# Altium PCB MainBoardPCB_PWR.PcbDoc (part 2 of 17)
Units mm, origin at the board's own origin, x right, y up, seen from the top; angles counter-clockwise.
Board outline 333.63 x 349.38 mm, 16 copper layers (L1, L2 (GND), L3 (Sign), L4 (GND), L5 (Sign), L6 (PWR/GND), L7(PWR/GND), L8 (PWR/GND), L9 (PWR/GND), L10 (PWR/GND), L11 (PWR/GND), L12 (Sign), L13 (GND), L14 (Sign), L15 (GND), L16), stack 2.503 mm thick; 2187 components, 1615 nets, 7987 pads, 1695 vias.
Unrouted connection lines stored in the file: 4757.
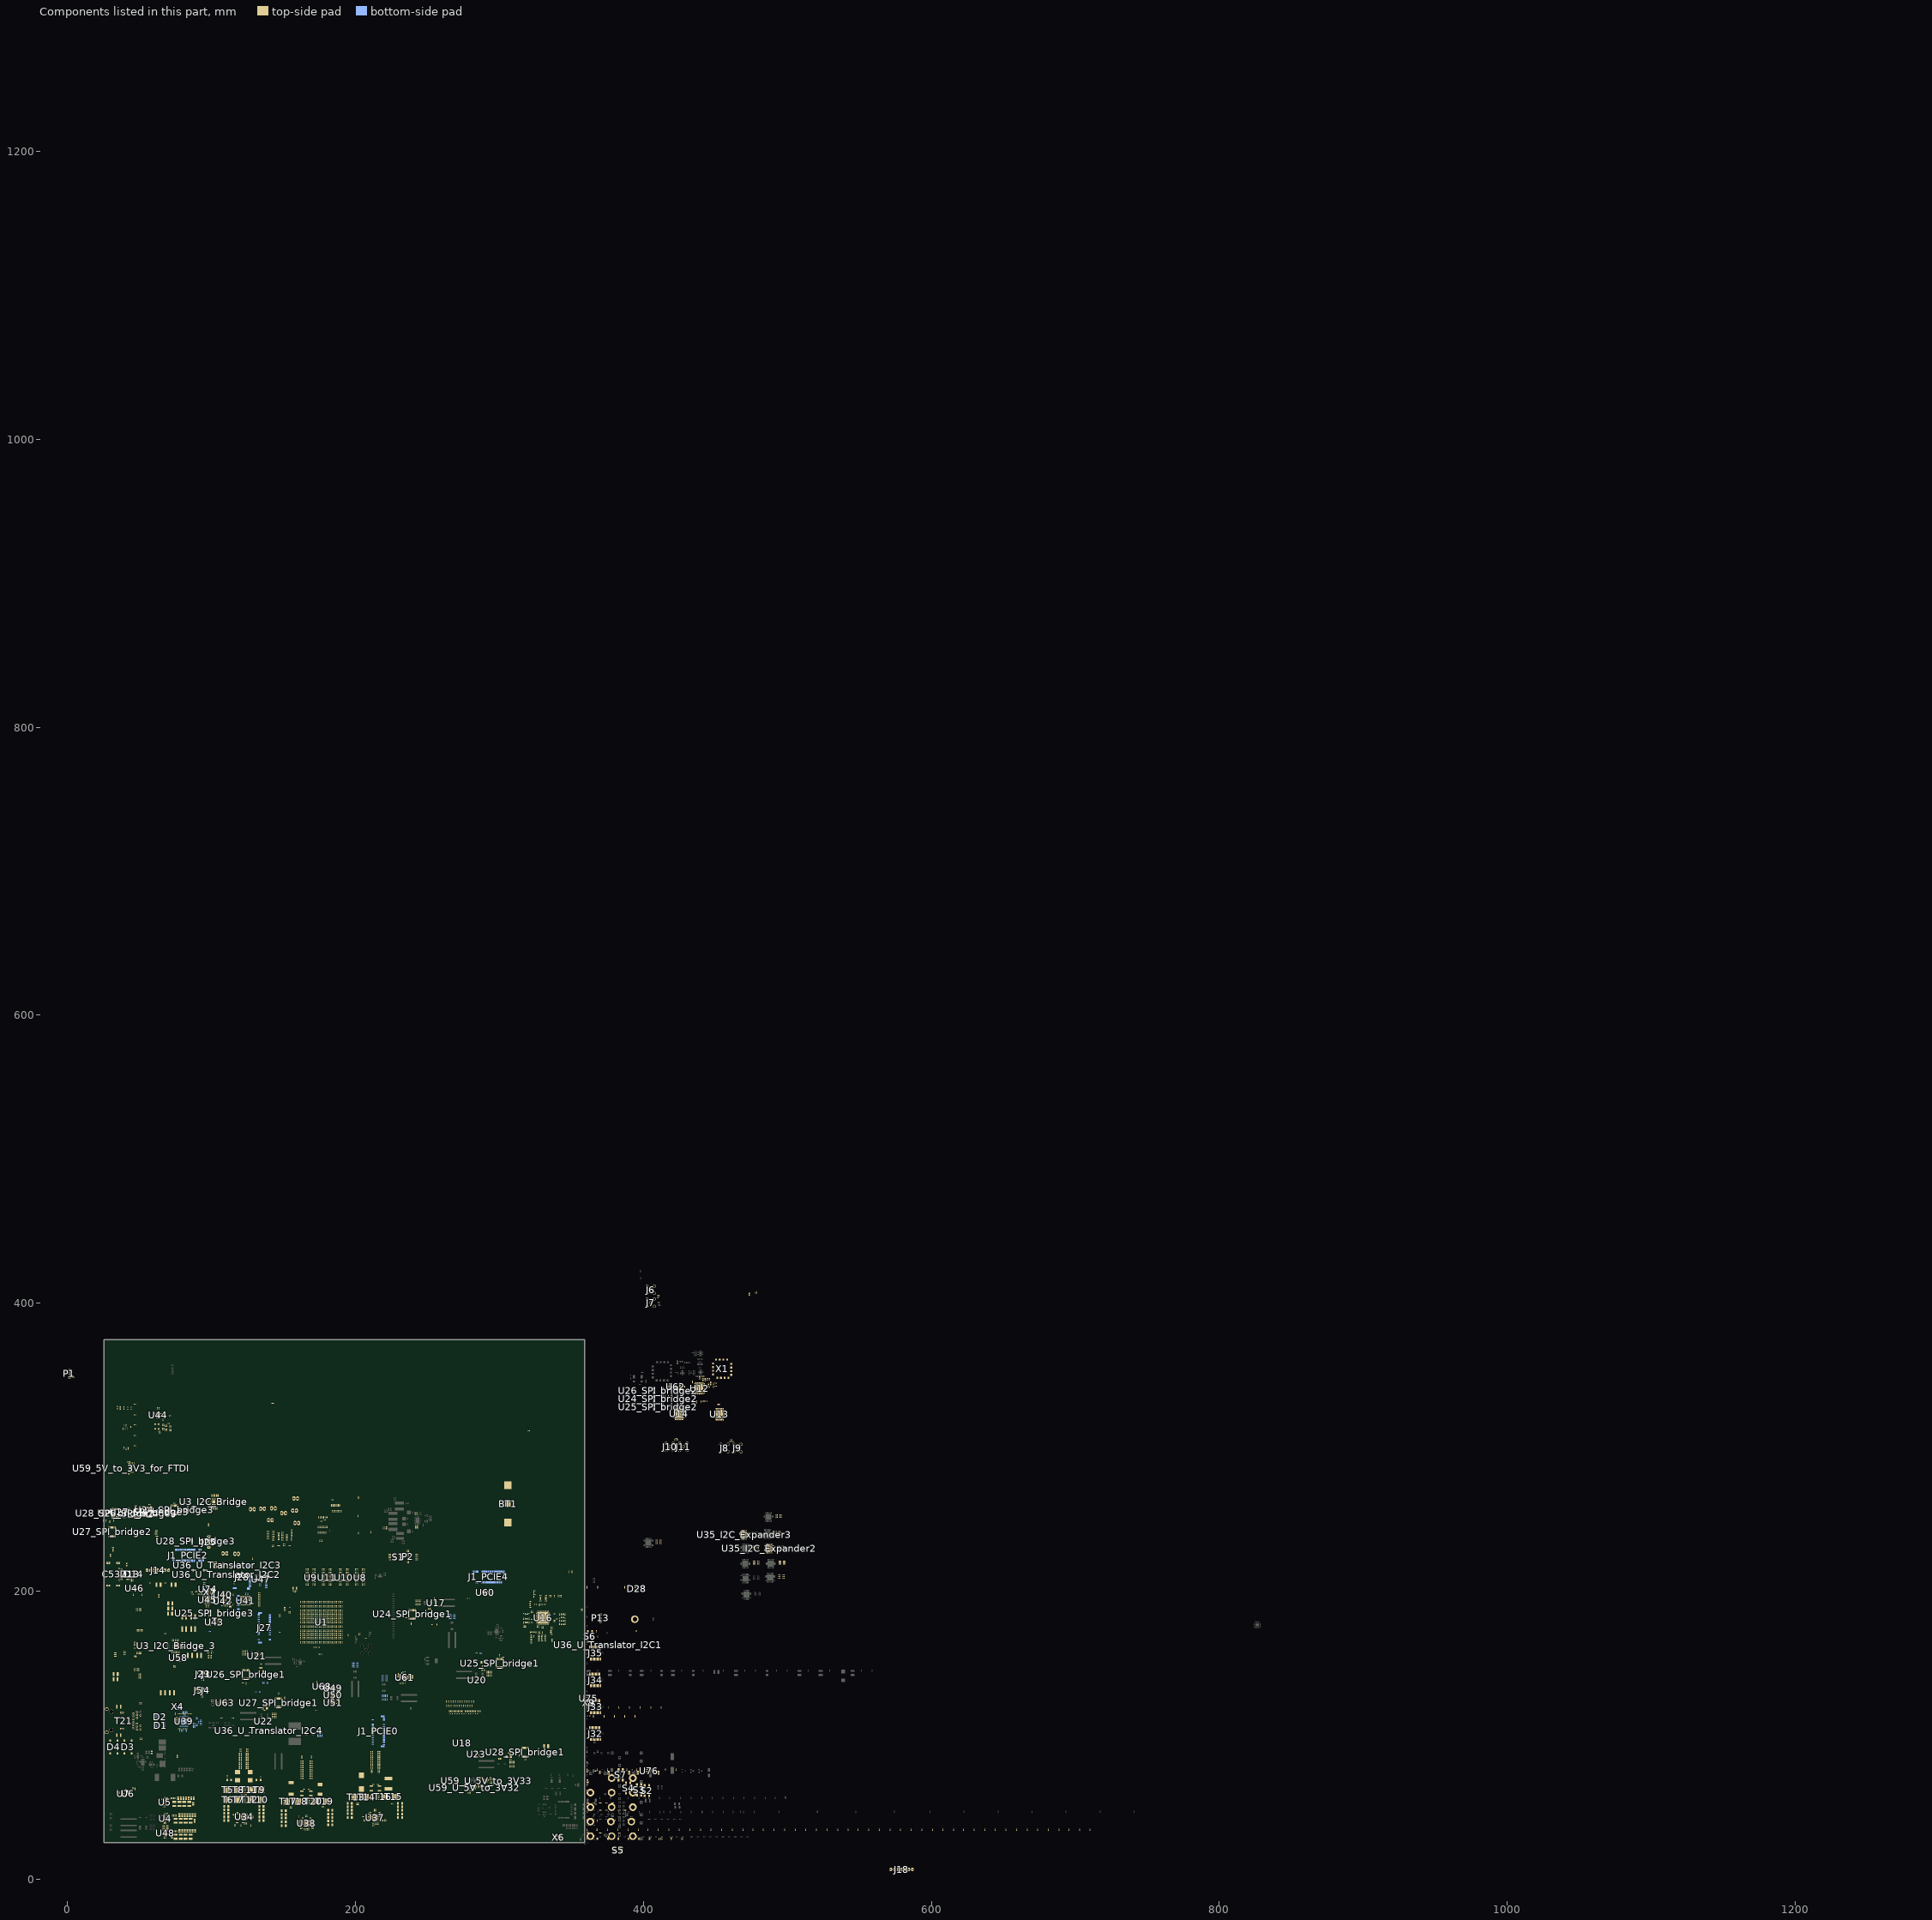
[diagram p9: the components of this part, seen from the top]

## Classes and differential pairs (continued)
net class Bank225_MGTREFx_to_C: CLK_Q225_T1_N CLK_Q225_T1_P
net class Bank225_MGTREFx_C: Bank225_MGTREF0_C_N Bank225_MGTREF0_C_P Bank225_MGTREF1_C_N Bank225_MGTREF1_C_P
net class Bank224_MGTREFx_to_C: CLK_Q224_T1_N CLK_Q224_T1_P
net class Bank224_MGTREFx_C: Bank224_MGTREF0_C_N Bank224_MGTREF0_C_P Bank224_MGTREF1_C_N Bank224_MGTREF1_C_P
net class Bank223_MGTREFx_to_C: CLK_Q223_T1_N CLK_Q223_T1_P
net class Bank223_MGTREFx_C: Bank223_MGTREF0_C_N Bank223_MGTREF0_C_P Bank223_MGTREF1_C_N Bank223_MGTREF1_C_P
component class U_Translator_I2C4: TP60_U_Translator_I2C4 TP61_U_Translator_I2C4 U36_U_Translator_I2C4
differential pair class Diff_90: USB_D USB_RX USB_RX_C USB_TX USB_TX_C
net class USB_2.0: USB_D_N USB_D_P
net class SYNC: SYNC_PCIE0_N SYNC_PCIE0_P SYNC_PCIE1_N SYNC_PCIE1_P SYNC_PCIE2_N SYNC_PCIE2_P SYNC_PCIE3_N SYNC_PCIE3_P SYNC_PCIE4_N SYNC_PCIE4_P
net class Single_45: USB_D_N USB_D_P USB_RX_C_N USB_RX_C_P USB_RX_N USB_RX_P USB_TX_C_N USB_TX_C_P USB_TX_N USB_TX_P
component class U_CAN: C585 P6 R446 R447 U63 U75
differential pair class Diff_100: B223_Rx0 B223_Rx1 B223_Rx2 B223_Rx3 B223_Tx0_to_C B223_Tx0C_to_B B223_Tx1_to_C B223_Tx1C_to_B B223_Tx2_to_C B223_Tx2C_to_B B223_Tx3_to_C B223_Tx3C_to_B B224_Rx0 B224_Rx1 B224_Rx2 B224_Rx3 B224_Tx0_to_C B224_Tx0C_to_B B224_Tx1_to_C B224_Tx1C_to_B B224_Tx2_to_C B224_Tx2C_to_B B224_Tx3_to_C B224_Tx3C_to_B B225_Rx0 B225_Rx1 B225_Rx2 B225_Rx3 B225_Tx0_to_C B225_Tx0C_to_B B225_Tx1_to_C B225_Tx1C_to_B B225_Tx2_to_C B225_Tx2C_to_B B225_Tx3_to_C B225_Tx3C_to_B Bank223_MGTREF0_C Bank223_MGTREF1_C Bank224_MGTREF0_C Bank224_MGTREF1_C Bank225_MGTREF0_C Bank225_MGTREF1_C Bank505_MGTRREF0_C Bank505_MGTRREF2_C Bank505_MGTRREF3_C CLK_100 CLK_Fanout_In CLK_GTR_T1 CLK_GTR_T2 CLK_GTR_T3 CLK_Hi_Rail1 CLK_Hi_Rail1_SysRef CLK_Hi_Rail2 CLK_Hi_Rail2_SysRef CLK_M_OSC_In CLK_NVME_Conn CLK_Q223_T1 CLK_Q224_T1 CLK_Q225_T1 CLK_Q226_T1 CLK_SMA0 CLK_SMA0_C CLK_SMA1 CLK_SMA1_C CLK_SMA2 CLK_SMA2_C Data_2_RX_PCIE0 Data_2_RX_PCIE1 Data_2_RX_PCIE2 Data_2_RX_PCIE3 Data_2_TX_PCIE0 Data_2_TX_PCIE1 Data_2_TX_PCIE2 Data_2_TX_PCIE3 Data_3_RX_PCIE0 Data_3_RX_PCIE1 Data_3_RX_PCIE2 Data_3_RX_PCIE3 Data_3_TX_PCIE0 Data_3_TX_PCIE1 Data_3_TX_PCIE2 Data_3_TX_PCIE3 LTC6952_1_REF LTC6952_2_REF LTC6952_2_REF_SMA LTC6952_3_REF LTC6952_3_REF_SMA NVME_C_RX_1 NVME_C_RX_O NVME_C_TX_1 NVME_C_TX_O NVMe_CLK NVMe_Rx_0 NVMe_Rx_1 NVMe_Tx_0 NVMe_Tx_1 Osc_in_Si53323_2 OSC_Out_DIV PCIE0_CLK PCIE0_Sync PCIE0_SysRef PCIE0_SysRef_FPGA PCIE1_CLK PCIE1_Sync PCIE1_SysRef PCIE1_SysRef_FPGA PCIE2_CLK PCIE2_Sync PCIE2_SysRef PCIE2_SysRef_FPGA PCIE3_CLK PCIE3_Sync PCIE3_SysRef PCIE3_SysRef_FPGA PCIE4_CLK PCIE4_Sync PCIE4_SysRef PCIE4_SysRef_FPGA RefClk_Si53323 SFP0_Rx SFP0_Tx SFP1_Rx SFP1_Tx SFP2_Rx SFP2_Tx SFP3_Rx SFP3_Tx SGMI_C_Rx SGMI_C_Tx SGMI_CLK_C_Out SGMI_CLK_Out SGMI_Rx SGMI_Tx Si53323_1_Q1 Si53323_1_Q2 Si53323_1_Q2_LVDS Si53323_2_CLK1 Si53323_2_Q1 Si53323_2_Q2 Si53323_2_Q2_LVDS SYNC_PCIE0 SYNC_PCIE1 SYNC_PCIE2 SYNC_PCIE3 SYNC_PCIE4 SYSREF_PCIE0 SYSREF_PCIE1 SYSREF_PCIE2 SYSREF_PCIE3 SYSREF_PCIE4 TD_A TD_B TD_C TD_D WR_LMK_CLK_HF1 WR_LMK_CLK_HF2 WR_LMK_CLK_IN WR_Source_CLK
channel class Translator_I2C: U_Translator_I2C1 U_Translator_I2C2 U_Translator_I2C3
channel class 5V_to_3V3: 5V_to_3V3_for_FTDI U_5V_to_3V32 U_5V_to_3V33
net class SYSREF: PCIE0_SysRef_N PCIE0_SysRef_P PCIE1_SysRef_N PCIE1_SysRef_P PCIE2_SysRef_N PCIE2_SysRef_P PCIE3_SysRef_N PCIE3_SysRef_P PCIE4_SysRef_N PCIE4_SysRef_P
net class SGMII_DATA_TO_C: SGMI_Rx_N SGMI_Rx_P SGMI_Tx_N SGMI_Tx_P
net class SGMII_DATA_C_FPGA: SGMI_C_Rx_N SGMI_C_Rx_P SGMI_C_Tx_N SGMI_C_Tx_P
net class Distr_to_Conn: PCIE0_CLK_N PCIE0_CLK_P PCIE1_CLK_N PCIE1_CLK_P PCIE2_CLK_N PCIE2_CLK_P PCIE3_CLK_N PCIE3_CLK_P PCIE4_CLK_N PCIE4_CLK_P
net class SFP_diff: SFP0_Rx_N SFP0_Rx_P SFP0_Tx_N SFP0_Tx_P SFP1_Rx_N SFP1_Rx_P SFP1_Tx_N SFP1_Tx_P SFP2_Rx_N SFP2_Rx_P SFP2_Tx_N SFP2_Tx_P SFP3_Rx_N SFP3_Rx_P SFP3_Tx_N SFP3_Tx_P
net class Conn_to_C: B223_Tx0_to_C_N B223_Tx0_to_C_P B223_Tx1_to_C_N B223_Tx1_to_C_P B223_Tx2_to_C_N B223_Tx2_to_C_P B223_Tx3_to_C_N B223_Tx3_to_C_P B224_Tx0_to_C_N B224_Tx0_to_C_P B224_Tx1_to_C_N B224_Tx1_to_C_P B224_Tx2_to_C_N B224_Tx2_to_C_P B224_Tx3_to_C_N B224_Tx3_to_C_P B225_Tx0_to_C_N B225_Tx0_to_C_P B225_Tx1_to_C_N B225_Tx1_to_C_P B225_Tx2_to_C_N B225_Tx2_to_C_P B225_Tx3_to_C_N B225_Tx3_to_C_P Data_2_TX_PCIE0_N Data_2_TX_PCIE0_P Data_2_TX_PCIE1_N Data_2_TX_PCIE1_P Data_2_TX_PCIE2_N Data_2_TX_PCIE2_P Data_2_TX_PCIE3_N Data_2_TX_PCIE3_P Data_3_TX_PCIE0_N Data_3_TX_PCIE0_P Data_3_TX_PCIE1_N Data_3_TX_PCIE1_P Data_3_TX_PCIE2_N Data_3_TX_PCIE2_P Data_3_TX_PCIE3_N Data_3_TX_PCIE3_P
net class C_to_Bank225: B225_Tx0C_to_B_N B225_Tx0C_to_B_P B225_Tx1C_to_B_N B225_Tx1C_to_B_P B225_Tx2C_to_B_N B225_Tx2C_to_B_P B225_Tx3C_to_B_N B225_Tx3C_to_B_P
net class C_to_Bank224: B224_Tx0C_to_B_N B224_Tx0C_to_B_P B224_Tx1C_to_B_N B224_Tx1C_to_B_P B224_Tx2C_to_B_N B224_Tx2C_to_B_P B224_Tx3C_to_B_N B224_Tx3C_to_B_P
net class C_to_Bank223: B223_Rx0_N B223_Rx0_P B223_Rx1_N B223_Rx1_P B223_Rx2_N B223_Rx2_P B223_Rx3_N B223_Rx3_P B223_Tx0C_to_B_N B223_Tx0C_to_B_P B223_Tx1C_to_B_N B223_Tx1C_to_B_P B223_Tx2C_to_B_N B223_Tx2C_to_B_P B223_Tx3C_to_B_N B223_Tx3C_to_B_P
net class Bank_to_Conn: B223_Rx0_N B223_Rx0_P B223_Rx1_N B223_Rx1_P B223_Rx2_N B223_Rx2_P B223_Rx3_N B223_Rx3_P B224_Rx0_N B224_Rx0_P B224_Rx1_N B224_Rx1_P B224_Rx2_N B224_Rx2_P B224_Rx3_N B224_Rx3_P B225_Rx0_N B225_Rx0_P B225_Rx1_N B225_Rx1_P B225_Rx2_N B225_Rx2_P B225_Rx3_N B225_Rx3_P Data_2_RX_PCIE0_N Data_2_RX_PCIE0_P Data_2_RX_PCIE1_N Data_2_RX_PCIE1_P Data_2_RX_PCIE2_N Data_2_RX_PCIE2_P Data_2_RX_PCIE3_N Data_2_RX_PCIE3_P Data_3_RX_PCIE0_N Data_3_RX_PCIE0_P Data_3_RX_PCIE1_N Data_3_RX_PCIE1_P Data_3_RX_PCIE2_N Data_3_RX_PCIE2_P Data_3_RX_PCIE3_N Data_3_RX_PCIE3_P PCIE0_Prsnt1 PCIE1_Prsnt1 PCIE2_Prsnt1 PCIE3_Prsnt1 PCIE4_Prsnt1
component class U_Translator_I2C3: TP60_U_Translator_I2C3 TP61_U_Translator_I2C3 U36_U_Translator_I2C3
component class U_Translator_I2C2: TP60_U_Translator_I2C2 TP61_U_Translator_I2C2 U36_U_Translator_I2C2
component class U_Translator_I2C1: TP60_U_Translator_I2C1 TP61_U_Translator_I2C1 U36_U_Translator_I2C1
component class U_TPS7A88_5V_Dual_3: C572 C573 C574 C575 C576 C577 C578 C579 R436 R437 R438 R439 R440 R441 U61
component class U_LT3042_12V_5V_LNLDO: C580 C581 C582 C583 C584 FB34 R442 R443 R444 R445 U62
component class U_ADP1741_3: C568 C569 C570 C571 FB33 R433 R434 U60
component class U_5V_to_3V33: C563_U_5V_to_3V33 C564_U_5V_to_3V33 C565_U_5V_to_3V33 C566_U_5V_to_3V33 C567_U_5V_to_3V33 R430_U_5V_to_3V33 R431_U_5V_to_3V33 R432_U_5V_to_3V33 U59_U_5V_to_3V33
component class U_5V_to_3V32: C563_U_5V_to_3V32 C564_U_5V_to_3V32 C565_U_5V_to_3V32 C566_U_5V_to_3V32 C567_U_5V_to_3V32 R430_U_5V_to_3V32 R431_U_5V_to_3V32 R432_U_5V_to_3V32 U59_U_5V_to_3V32
component class SPI_bridge3: R231_SPI_bridge3 R232_SPI_bridge3 R233_SPI_bridge3 R234_SPI_bridge3 R235_SPI_bridge3 R236_SPI_bridge3 R237_SPI_bridge3 R238_SPI_bridge3 R239_SPI_bridge3 R240_SPI_bridge3 TP50_SPI_bridge3 TP51_SPI_bridge3 TP52_SPI_bridge3 TP53_SPI_bridge3 TP54_SPI_bridge3 TP55_SPI_bridge3 TP56_SPI_bridge3 TP57_SPI_bridge3 TP58_SPI_bridge3 TP59_SPI_bridge3 U24_SPI_bridge3 U25_SPI_bridge3 U26_SPI_bridge3 U27_SPI_bridge3 U28_SPI_bridge3
component class Ram_Power: C219 C220 C221 C222 C223 C224 C225 C226 C227 C228 C229 C230 C231 C232 C233 C234 C235 C236 C237 C238 C239 C240 C241 C242 C243 C244 C245 C246 C247 C248 C249 C250 C251 C252 C253 C254 C255 C256 C257 C258 C259 C260 C261 C262 C263 C264 C265 C266 C782 C783 C784 C785 C786 C787 C788 C789 R165 R166 R167 R168 R169 R170 R171 R172
component class PS_Config: C531 C532 C533 C534 C535 C536 D5 D6 D7 D8 D9 D10 D11 D12 P2 P3 P4 P5 R346 R347 R348 R349 R350 R351 R352 R353 R354 R355 R356 R357 R358 R359 R360 R361 R367 R368 R369 R370 R371 R372 R373 R374 R375 R716 R717 R718 R719 R720 S1 S2 S3 S4 U43 U44 X5 X6
component class IMU: C561 C562 R425 R426 R429 R600 R601 U58
component class GTR: C525 C526 C527 C528 C529 C530 C649 C651 C653 C677 C715 C716 C717 C718 R69 R70 R126
component class "Bank 225": C291 C292 C293 C294 C295 C296 C297 C298 C299 C300 C301 C302
component class "Bank 224": C279 C280 C281 C282 C283 C284 C285 C286 C287 C288 C289 C290
component class "Bank 223": C267 C268 C269 C270 C271 C272 C273 C274 C275 C276 C277 C278
component class 5V_to_3V3_for_FTDI: C563_5V_to_3V3_for_FTDI C564_5V_to_3V3_for_FTDI C565_5V_to_3V3_for_FTDI C566_5V_to_3V3_for_FTDI C567_5V_to_3V3_for_FTDI R430_5V_to_3V3_for_FTDI R431_5V_to_3V3_for_FTDI R432_5V_to_3V3_for_FTDI U59_5V_to_3V3_for_FTDI
component class µSD: C544 C545 C546 C547 FB29 J28 R381 R382 R383 U47
component class U_Power_Ethernet: C550 C551 C552 C553 C554 C555 C654 C655 C656 C657 R391 R392 R393 R394 R396 R397 R399 R632 R633 R634 U49 U50 U51 U68
component class U_Power_ADP1850_Dual_2: C430 C431 C432 C433 C434 C435 C436 C437 C438 C439 C440 C441 C442 C443 C444 C445 C446 C447 C448 C449 C450 C451 C452 C453 C454 C455 C456 C457 C458 C459 C460 C461 C462 C463 C464 C465 C466 C467 C468 C469 C470 C548 C549 C645 C646 C647 C648 C650 C652 L19 L20 R302 R303 R306 R307 R310 R312 R313 R314 R315 R316 R317 R318 R625 R626 R627 R628 R629 R631 R686 R687 T17 T18 T19 T20 U38
component class U_HI_Curr_ADP1850_3: C389 C390 C391 C392 C393 C394 C395 C396 C397 C398 C399 C400 C401 C402 C403 C404 C405 C406 C407 C408 C409 C410 C411 C412 C413 C414 C415 C416 C417 C418 C419 C420 C421 C422 C423 C424 C425 C426 C427 C428 C429 C637 C638 C639 C640 C641 C642 C643 C644 L11 L12 R285 R287 R288 R289 R290 R292 R293 R294 R295 R296 R297 R298 R299 R300 R619 R620 R621 R622 R623 R624 T13 T14 T15 T16 U37
component class NVMe: J27 R541 R542
component class "Zasilanie CLK": C55 C56 C57 C58 C59 C60 C61 C62 C63 C64 C65 C66 C67 C68 C69 C70 C71 C72 C73 C74 C75 C76 C77 C78 C79 C80 C81 C82 C83 C84 C85 C86 C87 C88 C89 C90 C91 C92 C93 C94 C95 C96 C97 C98 C99 C100 C101 C102 C103 C104 C105 C106 C107 C108 C109 C110 C111 C112 C113 C114 C115 C116 C117 C118 C119 C120 C121 C122 C123 C124 C125 C126 C127 C128 C129 C130 C131 C132 C133 C134 C135 C136 C137 C138 C139 C140 C141 C142 C143 C144 C145 C146 C147 C148 C149 C150 C151 C152 C153 C154 C155 C156 C157 C158 C159 C160 C161 C162 C163 C164 C165 C166 C167 C168 C169 C170 C171 C172 C173 C174 C175 C176 C177 C178 C179 C180 C181 C182 C183 C184 C185 C186 C187 C188 C189 C190 C191 C192 C193 C194 C195 C196 C197 C198 C199 C200 C201 C202 C203 C204 C205 C206 FB2 FB3 FB4 FB5 FB6 FB7 FB8 FB9 FB10 FB11 FB12 FB13 FB14 FB15 FB16 FB17 FB18 FB19 FB20 FB21 FB22 FB35 FB36 R738 R739 R740 R741 R742 R743 U16
component class "Gigabit Eth": C471 C472 C473 C474 C475 C476 C479 C480 C481 C482 C483 C484 C485 C486 C487 C488 C489 C490 C491 C492 C493 C494 C495 C496 C497 C498 C499 C500 C501 C502 C503 C504 C505 C506 C507 C508 C509 C510 C511 C512 C513 C514 C790 D1 D2 D3 D4 R319 R320 R321 R322 R323 R324 R325 R326 R327 R328 R329 R330 R331 R332 R333 R334 R335 R336 R337 R338 R709 R710 R711 R712 R713 R714 R715 S7 T21 U39 U76 X4
component class Flash_Memory: C515 C516 C517 C518 C519 C520 C521 C522 C523 C524 C586 C587 FB25 R339 R340 R341 R342 R343 R344 R345 U40 U41 U42
component class PowerSelector: C4 C5 C6 C7 C8 C9 C10 C11 C12 C13 C14 C15 C16 C17 C18 C19 C20 C21 C22 C23 C24 C25 C26 C27 C28 C29 C30 C31 C32 C33 C34 C35 C766 C767 C768 C769 C770 C771 C772 C773 C774 C775 C776 C777 C778 C779 C780 C781 R11 R12 R13 R15 R17 R18 R19 R20 R21 R23 R25 R26 R27 R28 R29 R30 R630 R677 R678 R679 R680 R681 R682 R683 R684 R685 U4 U5 U6 U7 U48
component class USB3.0: C537 C538 C539 C540 C541 C542 C543 C728 C729 C730 C731 C732 C733 C734 C735 C736 C737 D13 D14 FB26 FB27 FB28 R376 R377 R378 R379 R380 R490 R491 U45 U46 U74 X7
channel class SPI_Muxes: SPI_bridge1 SPI_bridge2
channel class I2C_Expander: I2C_Expander2 I2C_Expander3 I2C_Expander4 I2C_Expander5
component class XilinxPower: B1 C627 C628 C629 C630 C631 C632 D28 FB38 FB39 FB40 FB41 FB42 R173 R276 R279 R282 R283 R286 R693 R694 R695 R696
component class "Xilinx Linux": J12 J13 J14 J15 J16 J17 J18 J19 J20 J21 J22 J23 J24 J25 P1 P13 R83 R84 R85 R86 R87 R88 R89 R90 R91 R92 R93 R94 R95 R96 R97 R98 R99 R100 R101 R102 R103 R104 R105 R106 R107 R108 R109 R110 R111 R112 R115 R116 R117 R118 R119 R120 R121 R122 R123 R362 R675 R737 R768 R769 R770 R771 R772 R773 R774 R775 R776 R777 R778 R779 R780 R781 R782 R783 R784 R785 R786 R787 R788 R789 R790 R791 R792 R793 R794 R795 R796 R797 R798 R799 R800 R801 R802 R803 R804 R805 R806 R807 R808 R809 R810 R811 R812 R813 R814 R815 R816 TP21 TP22 TP23 TP24 TP25 TP26 TP27 TP28 TP29 TP30 TP31 TP32 TP33 TP34 TP35 TP36 TP37 TP38 TP39 TP40 TP41 TP42
component class "WR CLK": C588 C589 C590 C591 C592 FB37 R1 R2 R125 R127 R128 R129 R130 R131 R132 R133 R134 R139 R311 R366 R498 R499 R540 R543 R544 R545 R692 S6 X9
component class U_HI_Curr_ADP1850_1: C345 C346 C347 C348 C349 C350 C351 C352 C353 C356 C357 C358 C359 C360 C361 C362 C363 C364 C365 C366 C367 C368 C369 C370 C371 C372 C373 C374 C375 C376 C377 C378 C379 C380 C381 C382 C383 C384 C385 C386 C387 C388 C633 C634 C635 C636 L9 L10 R268 R271 R272 R273 R275 R277 R278 R280 R610 R611 R612 R613 R614 R615 R616 T5 T6 T7 T8 T9 T10 T11 T12 U34
component class SPI_bridge2: R231_SPI_bridge2 R232_SPI_bridge2 R233_SPI_bridge2 R234_SPI_bridge2 R235_SPI_bridge2 R236_SPI_bridge2 R237_SPI_bridge2 R238_SPI_bridge2 R239_SPI_bridge2 R240_SPI_bridge2 TP50_SPI_bridge2 TP51_SPI_bridge2 TP52_SPI_bridge2 TP53_SPI_bridge2 TP54_SPI_bridge2 TP55_SPI_bridge2 TP56_SPI_bridge2 TP57_SPI_bridge2 TP58_SPI_bridge2 TP59_SPI_bridge2 U24_SPI_bridge2 U25_SPI_bridge2 U26_SPI_bridge2 U27_SPI_bridge2 U28_SPI_bridge2
component class SPI_bridge1: R231_SPI_bridge1 R232_SPI_bridge1 R233_SPI_bridge1 R234_SPI_bridge1 R235_SPI_bridge1 R236_SPI_bridge1 R237_SPI_bridge1 R238_SPI_bridge1 R239_SPI_bridge1 R240_SPI_bridge1 TP50_SPI_bridge1 TP51_SPI_bridge1 TP52_SPI_bridge1 TP53_SPI_bridge1 TP54_SPI_bridge1 TP55_SPI_bridge1 TP56_SPI_bridge1 TP57_SPI_bridge1 TP58_SPI_bridge1 TP59_SPI_bridge1 U24_SPI_bridge1 U25_SPI_bridge1 U26_SPI_bridge1 U27_SPI_bridge1 U28_SPI_bridge1
component class SFP3: C215 C216 C217 C218 J35 L7 L8 R155 R156 R157 R158 R161 R162 R163 R164
component class SFP2: C211 C212 C213 C214 J34 L5 L6 R145 R146 R147 R148 R151 R152 R153 R154
component class SFP1: C207 C208 C209 C210 J33 L3 L4 R135 R136 R137 R138 R141 R142 R143 R144
component class Ram: C36 R31 R32 R33 R34 R35 R36 R37 R38 R39 R40 R41 R42 R43 R44 R45 R46 R47 R48 R49 R50 R51 R52 R53 R54 R55 R56 R57 R58 R59 R60 R61 R62 R63 R64 U8 U9 U10 U11
component class Power4HighSpeed: R174 R175 R176 R177 R178 R179 R180 R181 R182 R183 R184 R185 R186 R187 R188 R189 R190 R191 R192 R193 R194 R195 R196 R197 R198 R199 R200 R201 R202 R203 R204 R205 R206 R207 R208 R209 R210 R211 R213 R215 R217 R219 R221 R222 R228 R602 R603 R604 R605 R606 U17 U20 U21 U22 U23
component class I2C_Expander2: C311_I2C_Expander2 U35_I2C_Expander2
component class I2C_Expander3: C311_I2C_Expander3 U35_I2C_Expander3
component class Ext_GPIO: R241 R242 R243 R244 R281 R400 R428 R492 R493 R494 R495 R496 R497 R500 R501 R502 R503 R504 R505 R508 R509 R510 R511 R512 R513 R516 R517 R518 R519 R520 R521 R524 R525 R526 R527 R528 R529 R599 R697 R698 R699 R700 R701 R702 R703 R704 R705 R706 R707 R708 R832 R833 R834 R835 R836 R837 R838 R839 R840 R841 TP62 TP63 TP64 TP65 TP66 TP67 TP68 TP69 TP70 TP71 TP72 TP73 TP74 TP75 TP76 TP77 TP78 TP79 TP80 TP81 TP82 TP83 TP84 TP85 TP86 TP87 TP88
component class HiCurrent: C331 C332 R14 R16 R22 R24 R266 R267 R269 R304 R388 R389 R390 R561 R562 R563 R564 R565 R566 R567 R568 R569 R570 R571 R572 R573 R574 R575 R576 R577 R578 R579 R580 R581 R582 R583 R584 R585 R586 R587 R588 R589 R590 R591 R592 S5 U18
component class PCIE4: C1_PCIE4 C2_PCIE4 C3_PCIE4 D1_PCIE4 FB1_PCIE4 J1_PCIE4 MP1_PCIE4 MP2_PCIE4 MP3_PCIE4
component class PCIE3: C1_PCIE3 C2_PCIE3 C3_PCIE3 D1_PCIE3 FB1_PCIE3 MP1_PCIE3 MP2_PCIE3 MP3_PCIE3
component class PCIE2: C1_PCIE2 C2_PCIE2 C3_PCIE2 D1_PCIE2 FB1_PCIE2 J1_PCIE2 MP1_PCIE2 MP2_PCIE2 MP3_PCIE2
component class PCIE1: C1_PCIE1 C2_PCIE1 C3_PCIE1 D1_PCIE1 FB1_PCIE1 MP1_PCIE1 MP2_PCIE1 MP3_PCIE1
component class PCIE0: C1_PCIE0 C2_PCIE0 C3_PCIE0 D1_PCIE0 FB1_PCIE0 J1_PCIE0 MP1_PCIE0 MP2_PCIE0 MP3_PCIE0
component class ClockDistrib: C41 C42 C43 C44 C45 C46 C47 C48 C49 C50 C51 C52 C53 C54 C334 C335 C593 C594 J2 J3 J4 J5 J6 J7 J8 J9 J10 J11 R75 R76 R77 R78 R79 R80 R81 R82 R270 R532 R533 R534 R535 R536 R537 R539 TP19 TP20 U12 U13 U14 X1
channel class PCIe: PCIE0 PCIE1 PCIE2 PCIE3 PCIE4
channel class I2C_Bridge: I2C_Bridge I2C_Bridge_3
component class "Bank 226": U1
component class SFP0: C37 C38 C39 C40 J32 L1 L2 R65 R66 R67 R68 R71 R72 R73 R74
component class I2C_Bridge_3: C303_I2C_Bridge_3 R3_I2C_Bridge_3 R4_I2C_Bridge_3 R5_I2C_Bridge_3 R6_I2C_Bridge_3 R7_I2C_Bridge_3 R8_I2C_Bridge_3 R9_I2C_Bridge_3 R10_I2C_Bridge_3 R223_I2C_Bridge_3 R224_I2C_Bridge_3 R225_I2C_Bridge_3 R226_I2C_Bridge_3 R227_I2C_Bridge_3 R558_I2C_Bridge_3 R559_I2C_Bridge_3 R560_I2C_Bridge_3 TP1_I2C_Bridge_3 TP2_I2C_Bridge_3 TP3_I2C_Bridge_3 TP4_I2C_Bridge_3 TP5_I2C_Bridge_3 TP6_I2C_Bridge_3 TP7_I2C_Bridge_3 TP8_I2C_Bridge_3 TP9_I2C_Bridge_3 TP10_I2C_Bridge_3 TP11_I2C_Bridge_3 TP12_I2C_Bridge_3 TP13_I2C_Bridge_3 TP14_I2C_Bridge_3 TP15_I2C_Bridge_3 TP16_I2C_Bridge_3 TP17_I2C_Bridge_3 TP18_I2C_Bridge_3 U3_I2C_Bridge_3
component class I2C_Bridge: C303_I2C_Bridge R3_I2C_Bridge R4_I2C_Bridge R5_I2C_Bridge R6_I2C_Bridge R7_I2C_Bridge R8_I2C_Bridge R9_I2C_Bridge R10_I2C_Bridge R223_I2C_Bridge R224_I2C_Bridge R225_I2C_Bridge R226_I2C_Bridge R227_I2C_Bridge R558_I2C_Bridge R559_I2C_Bridge R560_I2C_Bridge TP1_I2C_Bridge TP2_I2C_Bridge TP3_I2C_Bridge TP4_I2C_Bridge TP5_I2C_Bridge TP6_I2C_Bridge TP7_I2C_Bridge TP8_I2C_Bridge TP9_I2C_Bridge TP10_I2C_Bridge TP11_I2C_Bridge TP12_I2C_Bridge TP13_I2C_Bridge TP14_I2C_Bridge TP15_I2C_Bridge TP16_I2C_Bridge TP17_I2C_Bridge TP18_I2C_Bridge U3_I2C_Bridge
differential pair PCIE1_SysRef: +PCIE1_SysRef_P -PCIE1_SysRef_N
differential pair PCIE1_CLK: +PCIE1_CLK_P -PCIE1_CLK_N
differential pair PCIE0_SysRef: +PCIE0_SysRef_P -PCIE0_SysRef_N
differential pair PCIE0_CLK: +PCIE0_CLK_P -PCIE0_CLK_N
differential pair Data_3_TX_PCIE3: +Data_3_TX_PCIE3_P -Data_3_TX_PCIE3_N
differential pair Data_3_TX_PCIE2: +Data_3_TX_PCIE2_P -Data_3_TX_PCIE2_N
differential pair Data_3_TX_PCIE1: +Data_3_TX_PCIE1_P -Data_3_TX_PCIE1_N
differential pair Data_3_TX_PCIE0: +Data_3_TX_PCIE0_P -Data_3_TX_PCIE0_N
differential pair Data_3_RX_PCIE3: +Data_3_RX_PCIE3_P -Data_3_RX_PCIE3_N
differential pair Data_3_RX_PCIE2: +Data_3_RX_PCIE2_P -Data_3_RX_PCIE2_N
differential pair Data_3_RX_PCIE1: +Data_3_RX_PCIE1_P -Data_3_RX_PCIE1_N
differential pair Data_3_RX_PCIE0: +Data_3_RX_PCIE0_P -Data_3_RX_PCIE0_N
differential pair Data_2_TX_PCIE3: +Data_2_TX_PCIE3_P -Data_2_TX_PCIE3_N
differential pair Data_2_TX_PCIE2: +Data_2_TX_PCIE2_P -Data_2_TX_PCIE2_N
differential pair Data_2_TX_PCIE1: +Data_2_TX_PCIE1_P -Data_2_TX_PCIE1_N
differential pair Data_2_TX_PCIE0: +Data_2_TX_PCIE0_P -Data_2_TX_PCIE0_N
differential pair Data_2_RX_PCIE3: +Data_2_RX_PCIE3_P -Data_2_RX_PCIE3_N
differential pair Data_2_RX_PCIE2: +Data_2_RX_PCIE2_P -Data_2_RX_PCIE2_N
differential pair Data_2_RX_PCIE1: +Data_2_RX_PCIE1_P -Data_2_RX_PCIE1_N
differential pair Data_2_RX_PCIE0: +Data_2_RX_PCIE0_P -Data_2_RX_PCIE0_N
differential pair NVME_C_RX_1: +NVME_C_RX_1_P -NVME_C_RX_1_N
differential pair DDR4_DQS_8: +DDR4_DQS_8_P -DDR4_DQS_8_N
differential pair DDR4_DQS_4: +DDR4_DQS_4_P -DDR4_DQS_4_N
differential pair NVME_C_TX_O: +NVME_C_TX_O_P -NVME_C_TX_O_N
differential pair NVME_C_TX_1: +NVME_C_TX_1_P -NVME_C_TX_1_N
differential pair NVME_C_RX_O: +NVME_C_RX_O_P -NVME_C_RX_O_N
differential pair WR_Source_CLK: +WR_Source_CLK_P -WR_Source_CLK_N
differential pair WR_LMK_CLK_IN: +WR_LMK_CLK_IN_P -WR_LMK_CLK_IN_N
differential pair WR_LMK_CLK_HF2: +WR_LMK_CLK_HF2_P -WR_LMK_CLK_HF2_N
differential pair WR_LMK_CLK_HF1: +WR_LMK_CLK_HF1_P -WR_LMK_CLK_HF1_N
differential pair PCIE4_SysRef_FPGA: +PCIE4_SysRef_FPGA_P -PCIE4_SysRef_FPGA_N
differential pair PCIE3_SysRef_FPGA: +PCIE3_SysRef_FPGA_P -PCIE3_SysRef_FPGA_N
differential pair PCIE2_SysRef_FPGA: +PCIE2_SysRef_FPGA_P -PCIE2_SysRef_FPGA_N
differential pair PCIE1_SysRef_FPGA: +PCIE1_SysRef_FPGA_P -PCIE1_SysRef_FPGA_N
differential pair PCIE0_SysRef_FPGA: +PCIE0_SysRef_FPGA_P -PCIE0_SysRef_FPGA_N
differential pair CLK_Fanout_In: +CLK_Fanout_In_P -CLK_Fanout_In_N
differential pair LTC6952_3_REF: +LTC6952_3_REF_P -LTC6952_3_REF_N
differential pair LTC6952_3_REF_SMA: +LTC6952_3_REF_SMA_P -LTC6952_3_REF_SMA_N
differential pair LTC6952_2_REF: +LTC6952_2_REF_P -LTC6952_2_REF_N
differential pair LTC6952_2_REF_SMA: +LTC6952_2_REF_SMA_P -LTC6952_2_REF_SMA_N
differential pair LTC6952_1_REF: +LTC6952_1_REF_P -LTC6952_1_REF_N
differential pair CLK_NVME_Conn: +CLK_NVME_Conn_P -CLK_NVME_Conn_N
differential pair CLK_Hi_Rail2: +CLK_Hi_Rail2_P -CLK_Hi_Rail2_N
differential pair CLK_Hi_Rail2_SysRef: +CLK_Hi_Rail2_SysRef_P -CLK_Hi_Rail2_SysRef_N
differential pair CLK_Hi_Rail1: +CLK_Hi_Rail1_P -CLK_Hi_Rail1_N
differential pair CLK_Hi_Rail1_SysRef: +CLK_Hi_Rail1_SysRef_P -CLK_Hi_Rail1_SysRef_N
differential pair CLK_GTR_T3: +CLK_GTR_T3_P -CLK_GTR_T3_N
differential pair CLK_GTR_T2: +CLK_GTR_T2_P -CLK_GTR_T2_N
differential pair CLK_GTR_T1: +CLK_GTR_T1_P -CLK_GTR_T1_N
differential pair Si53323_2_Q2_LVDS: +Si53323_2_Q2_LVDS_P -Si53323_2_Q2_LVDS_N
differential pair Si53323_1_Q2_LVDS: +Si53323_1_Q2_LVDS_P -Si53323_1_Q2_LVDS_N
differential pair Si53323_2_CLK1: +Si53323_2_CLK1_P -Si53323_2_CLK1_N
differential pair OSC_Out_DIV: +OSC_Out_DIV_P -OSC_Out_DIV_N
differential pair Osc_in_Si53323_2: +Osc_in_Si53323_2_P -Osc_in_Si53323_2_N
differential pair CLK_SMA2: +CLK_SMA2_P -CLK_SMA2_N
differential pair CLK_SMA2_C: +CLK_SMA2_C_P -CLK_SMA2_C_N
differential pair CLK_SMA1: +CLK_SMA1_P -CLK_SMA1_N
differential pair CLK_SMA1_C: +CLK_SMA1_C_P -CLK_SMA1_C_N
differential pair CLK_SMA0: +CLK_SMA0_P -CLK_SMA0_N
differential pair CLK_SMA0_C: +CLK_SMA0_C_P -CLK_SMA0_C_N
differential pair DDR4_DQS_7: +DDR4_DQS_7_P -DDR4_DQS_7_N
differential pair DDR4_DQS_6: +DDR4_DQS_6_P -DDR4_DQS_6_N
differential pair DDR4_DQS_5: +DDR4_DQS_5_P -DDR4_DQS_5_N
differential pair DDR4_DQS_3: +DDR4_DQS_3_P -DDR4_DQS_3_N
differential pair DDR4_DQS_2: +DDR4_DQS_2_P -DDR4_DQS_2_N
differential pair DDR4_DQS_1: +DDR4_DQS_1_P -DDR4_DQS_1_N
differential pair DDR4_DQS_0: +DDR4_DQS_0_P -DDR4_DQS_0_N
differential pair DDR4_CK: +DDR4_CK_P -DDR4_CK_N
differential pair Si53323_2_Q2: +Si53323_2_Q2_P -Si53323_2_Q2_N
differential pair Si53323_2_Q1: +Si53323_2_Q1_P -Si53323_2_Q1_N
differential pair Si53323_1_Q2: +Si53323_1_Q2_P -Si53323_1_Q2_N
differential pair Si53323_1_Q1: +Si53323_1_Q1_P -Si53323_1_Q1_N
differential pair RefClk_Si53323: +RefClk_Si53323_P -RefClk_Si53323_N
differential pair USB_TX: +USB_TX_P -USB_TX_N
differential pair USB_RX: +USB_RX_P -USB_RX_N
differential pair NVMe_Tx_1: +NVMe_Tx_1_P -NVMe_Tx_1_N
differential pair NVMe_Tx_0: +NVMe_Tx_0_P -NVMe_Tx_0_N
differential pair NVMe_Rx_1: +NVMe_Rx_1_P -NVMe_Rx_1_N
differential pair NVMe_Rx_0: +NVMe_Rx_0_P -NVMe_Rx_0_N
differential pair CLK_Q226_T1: +CLK_Q226_T1_P -CLK_Q226_T1_N
differential pair CLK_Q225_T1: +CLK_Q225_T1_P -CLK_Q225_T1_N
differential pair CLK_Q224_T1: +CLK_Q224_T1_P -CLK_Q224_T1_N
differential pair CLK_Q223_T1: +CLK_Q223_T1_P -CLK_Q223_T1_N
differential pair Bank505_MGTRREF3_C: +Bank505_MGTRREF3_C_P -Bank505_MGTRREF3_C_N
differential pair Bank505_MGTRREF2_C: +Bank505_MGTRREF2_C_P -Bank505_MGTRREF2_C_N
differential pair Bank505_MGTRREF0_C: +Bank505_MGTRREF0_C_P -Bank505_MGTRREF0_C_N
differential pair Bank225_MGTREF1_C: +Bank225_MGTREF1_C_P -Bank225_MGTREF1_C_N
differential pair Bank225_MGTREF0_C: +Bank225_MGTREF0_C_P -Bank225_MGTREF0_C_N
differential pair Bank224_MGTREF1_C: +Bank224_MGTREF1_C_P -Bank224_MGTREF1_C_N
differential pair Bank224_MGTREF0_C: +Bank224_MGTREF0_C_P -Bank224_MGTREF0_C_N
differential pair Bank223_MGTREF1_C: +Bank223_MGTREF1_C_P -Bank223_MGTREF1_C_N
differential pair Bank223_MGTREF0_C: +Bank223_MGTREF0_C_P -Bank223_MGTREF0_C_N
differential pair USB_TX_C: +USB_TX_C_P -USB_TX_C_N
differential pair USB_RX_C: +USB_RX_C_P -USB_RX_C_N
differential pair USB_D: +USB_D_P -USB_D_N
differential pair SYNC_PCIE4: +SYNC_PCIE4_P -SYNC_PCIE4_N
differential pair SYNC_PCIE3: +SYNC_PCIE3_P -SYNC_PCIE3_N
differential pair SYNC_PCIE2: +SYNC_PCIE2_P -SYNC_PCIE2_N
differential pair SYNC_PCIE1: +SYNC_PCIE1_P -SYNC_PCIE1_N
differential pair SYNC_PCIE0: +SYNC_PCIE0_P -SYNC_PCIE0_N
differential pair PCIE4_SysRef: +PCIE4_SysRef_P -PCIE4_SysRef_N
differential pair PCIE3_SysRef: +PCIE3_SysRef_P -PCIE3_SysRef_N
differential pair PCIE2_SysRef: +PCIE2_SysRef_P -PCIE2_SysRef_N
differential pair TD_D: +TD_D_P -TD_D_N
differential pair TD_C: +TD_C_P -TD_C_N
differential pair TD_B: +TD_B_P -TD_B_N
differential pair TD_A: +TD_A_P -TD_A_N
differential pair SGMI_Tx: +SGMI_Tx_P -SGMI_Tx_N
differential pair SGMI_Rx: +SGMI_Rx_P -SGMI_Rx_N
differential pair SGMI_C_Tx: +SGMI_C_Tx_P -SGMI_C_Tx_N
differential pair SGMI_C_Rx: +SGMI_C_Rx_P -SGMI_C_Rx_N
differential pair SFP3_Tx: +SFP3_Tx_P -SFP3_Tx_N
differential pair SFP3_Rx: +SFP3_Rx_P -SFP3_Rx_N
differential pair SFP2_Tx: +SFP2_Tx_P -SFP2_Tx_N
differential pair SFP2_Rx: +SFP2_Rx_P -SFP2_Rx_N
differential pair SFP1_Tx: +SFP1_Tx_P -SFP1_Tx_N
differential pair SFP1_Rx: +SFP1_Rx_P -SFP1_Rx_N
differential pair SFP0_Tx: +SFP0_Tx_P -SFP0_Tx_N
differential pair SFP0_Rx: +SFP0_Rx_P -SFP0_Rx_N
differential pair PCIE4_CLK: +PCIE4_CLK_P -PCIE4_CLK_N
differential pair PCIE3_CLK: +PCIE3_CLK_P -PCIE3_CLK_N
differential pair PCIE2_CLK: +PCIE2_CLK_P -PCIE2_CLK_N
differential pair B225_Tx3C_to_B: +B225_Tx3C_to_B_P -B225_Tx3C_to_B_N
differential pair B225_Tx3_to_C: +B225_Tx3_to_C_P -B225_Tx3_to_C_N
differential pair B225_Tx2C_to_B: +B225_Tx2C_to_B_P -B225_Tx2C_to_B_N
differential pair B225_Tx2_to_C: +B225_Tx2_to_C_P -B225_Tx2_to_C_N
differential pair B225_Tx1C_to_B: +B225_Tx1C_to_B_P -B225_Tx1C_to_B_N
differential pair B225_Tx1_to_C: +B225_Tx1_to_C_P -B225_Tx1_to_C_N
differential pair B225_Tx0C_to_B: +B225_Tx0C_to_B_P -B225_Tx0C_to_B_N
differential pair B225_Tx0_to_C: +B225_Tx0_to_C_P -B225_Tx0_to_C_N
differential pair B225_Rx3: +B225_Rx3_P -B225_Rx3_N
differential pair B225_Rx2: +B225_Rx2_P -B225_Rx2_N
differential pair B225_Rx1: +B225_Rx1_P -B225_Rx1_N
differential pair B225_Rx0: +B225_Rx0_P -B225_Rx0_N
differential pair B224_Tx3C_to_B: +B224_Tx3C_to_B_P -B224_Tx3C_to_B_N
differential pair B224_Tx3_to_C: +B224_Tx3_to_C_P -B224_Tx3_to_C_N
differential pair B224_Tx2C_to_B: +B224_Tx2C_to_B_P -B224_Tx2C_to_B_N
differential pair B224_Tx2_to_C: +B224_Tx2_to_C_P -B224_Tx2_to_C_N
differential pair B224_Tx1C_to_B: +B224_Tx1C_to_B_P -B224_Tx1C_to_B_N
differential pair B224_Tx1_to_C: +B224_Tx1_to_C_P -B224_Tx1_to_C_N
differential pair B224_Tx0C_to_B: +B224_Tx0C_to_B_P -B224_Tx0C_to_B_N
differential pair B224_Tx0_to_C: +B224_Tx0_to_C_P -B224_Tx0_to_C_N
differential pair B224_Rx3: +B224_Rx3_P -B224_Rx3_N
differential pair B224_Rx2: +B224_Rx2_P -B224_Rx2_N
differential pair B224_Rx1: +B224_Rx1_P -B224_Rx1_N
differential pair B224_Rx0: +B224_Rx0_P -B224_Rx0_N
differential pair B223_Tx3C_to_B: +B223_Tx3C_to_B_P -B223_Tx3C_to_B_N
differential pair B223_Tx3_to_C: +B223_Tx3_to_C_P -B223_Tx3_to_C_N
differential pair B223_Tx2C_to_B: +B223_Tx2C_to_B_P -B223_Tx2C_to_B_N
differential pair B223_Tx2_to_C: +B223_Tx2_to_C_P -B223_Tx2_to_C_N
differential pair B223_Tx1C_to_B: +B223_Tx1C_to_B_P -B223_Tx1C_to_B_N
differential pair B223_Tx1_to_C: +B223_Tx1_to_C_P -B223_Tx1_to_C_N
differential pair B223_Tx0C_to_B: +B223_Tx0C_to_B_P -B223_Tx0C_to_B_N
differential pair B223_Tx0_to_C: +B223_Tx0_to_C_P -B223_Tx0_to_C_N
differential pair B223_Rx3: +B223_Rx3_P -B223_Rx3_N
differential pair B223_Rx2: +B223_Rx2_P -B223_Rx2_N
differential pair B223_Rx1: +B223_Rx1_P -B223_Rx1_N
differential pair B223_Rx0: +B223_Rx0_P -B223_Rx0_N

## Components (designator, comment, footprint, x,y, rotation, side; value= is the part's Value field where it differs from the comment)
B1 "TS920E-FL27E" Battery 349.463,213.385 r0 top
BT1 "79523141" 79523141 305.791,260.553 r90 top
C1_PCIE0 "100nF" "CAP 0402/1005 RF" 251.445,189.325 r0 top (schematic designator C1)
C1_PCIE1 "100nF" "CAP 0402/1005 RF" 288.662,146.389 r180 top (schematic designator C1)
C1_PCIE2 "100nF" "CAP 0402/1005 RF" 134.494,149.272 r0 top (schematic designator C1)
C1_PCIE3 "100nF" "CAP 0402/1005 RF" 136.906,117.094 r180 top (schematic designator C1)
C1_PCIE4 "100nF" "CAP 0402/1005 RF" 307.583,83.058 r180 top (schematic designator C1)
C2_PCIE0 "2.2uF" "CAP 1206/3216 - 0.8MM" 251.191,184.626 r0 top (schematic designator C2)
C2_PCIE1 "2.2uF" "CAP 1206/3216 - 0.8MM" 288.925,150.58 r180 top (schematic designator C2)
C2_PCIE2 "2.2uF" "CAP 1206/3216 - 0.8MM" 134.503,144.065 r0 top (schematic designator C2)
C2_PCIE3 "2.2uF" "CAP 1206/3216 - 0.8MM" 137.033,118.745 r180 top (schematic designator C2)
C2_PCIE4 "2.2uF" "CAP 1206/3216 - 0.8MM" 306.46,85.15 r180 top (schematic designator C2)
C3_PCIE0 "4.7uF" "CAP 0603/1608 RF" 251.318,187.547 r0 top (schematic designator C3)
C3_PCIE1 "4.7uF" "CAP 0603/1608 RF" 288.798,147.913 r180 top (schematic designator C3)
C3_PCIE2 "4.7uF" "CAP 0603/1608 RF" 134.259,141.144 r0 top (schematic designator C3)
C3_PCIE3 "4.7uF" "CAP 0603/1608 RF" 137.033,122.936 r180 top (schematic designator C3)
C3_PCIE4 "4.7uF" "CAP 0603/1608 RF" 307.085,87.503 r180 top (schematic designator C3)
C4 "22uF" "CAP 1210/3225 - 1MM" 84.662,52.238 r270 top
C5 "22uF" "CAP 1210/3225 - 1MM" 81.167,52.238 r270 top
C6 "22uF" "CAP 1210/3225 - 1MM" 74.299,52.238 r270 top
C7 "22uF" "CAP 1210/3225 - 1MM" 77.727,52.238 r270 top
C8 "100nF" "CAP 0402/1005 RF" 71.883,56.132 r270 top
C9 "100nF" "CAP 0402/1005 RF" 74.728,56.132 r270 top
C10 "100nF" "CAP 0402/1005 RF" 73.799,56.132 r270 top
C11 "100nF" "CAP 0402/1005 RF" 72.863,56.132 r270 top
C12 "22uF" "CAP 1210/3225 - 1MM" 85.543,40.55 r270 top
C13 "22uF" "CAP 1210/3225 - 1MM" 78.635,40.555 r270 top
C14 "22uF" "CAP 1210/3225 - 1MM" 75.208,40.55 r270 top
C15 "22uF" "CAP 1210/3225 - 1MM" 82.075,40.545 r270 top
C16 "100nF" "CAP 0402/1005 RF" 72.791,44.154 r270 top
C17 "100nF" "CAP 0402/1005 RF" 75.626,44.154 r270 top
C18 "100nF" "CAP 0402/1005 RF" 74.627,44.154 r270 top
C19 "100nF" "CAP 0402/1005 RF" 73.722,44.154 r270 top
C20 "10uF" "CAP 0805/2012 RF" 87.298,52.238 r90 top
C21 "10uF" "CAP 0805/2012 RF" 84.135,56.147 r270 top
C22 "10uF" "CAP 0805/2012 RF" 85.885,56.177 r270 top
C23 "10uF" "CAP 0805/2012 RF" 78.794,56.178 r270 top
C24 "4.7uF" "CAP 0805/2012 RF" 82.393,56.177 r270 top
C25 "4.7uF" "CAP 0805/2012 RF" 80.603,56.178 r270 top
C26 "4.7uF" "CAP 0805/2012 RF" 76.899,56.177 r270 top
C27 "4.7uF" "CAP 0805/2012 RF" 87.673,56.178 r270 top
C28 "10uF" "CAP 0805/2012 RF" 81.512,44.411 r270 top
C29 "10uF" "CAP 0805/2012 RF" 83.325,44.411 r270 top
C30 "10uF" "CAP 0805/2012 RF" 86.82,44.411 r270 top
C31 "10uF" "CAP 0805/2012 RF" 88.282,40.555 r90 top
C32 "4.7uF" "CAP 0805/2012 RF" 85.07,44.411 r270 top
C33 "4.7uF" "CAP 0805/2012 RF" 79.702,44.411 r270 top
C34 "4.7uF" "CAP 0805/2012 RF" 77.807,44.411 r270 top
C35 "4.7uF" "CAP 0805/2012 RF" 88.582,44.411 r270 top
C36 "10nF" "CAP 0402/1005 RF" 181.975,242.343 r90 top
C37 "100nF" "CAP 0402/1005 RF" 28.829,139.7 r0 top
C38 "22uF" "CAP 1210/3225 - 1MM" 33.401,138.938 r0 top
C39 "100nF" "CAP 0402/1005 RF" 38.1,138.811 r0 top
C40 "22uF" "CAP 1210/3225 - 1MM" 33.453,142.367 r0 top
C41 "1uF" "CAP 0402/1005 RF" 93.548,138.573 r270 top
C42 "1uF" "CAP 0402/1005 RF" 94.448,138.573 r270 top
C43 "1uF" "CAP 0402/1005 RF" 93.998,126.879 r270 top
C44 "1uF" "CAP 0402/1005 RF" 93.098,126.879 r270 top
C45 "5.6nF" "CAP 0402/1005 RF" 445.541,346.835 r180 top
C46 "200pF" "CAP 0402/1005 RF" 445.541,347.735 r180 top
C47 "1uF" "CAP 0402/1005 RF" 409.846,404.163 r270 top
C48 "1uF" "CAP 0402/1005 RF" 409.846,405.843 r90 top
C49 "1uF" "CAP 0402/1005 RF" 461.926,303.962 r0 top
C50 "1uF" "CAP 0402/1005 RF" 460.246,303.962 r180 top
C51 "1uF" "CAP 0402/1005 RF" 423.667,305.062 r0 top
C52 "1uF" "CAP 0402/1005 RF" 421.987,305.062 r180 top
C53 "1uF" "CAP 0402/1005 RF" 438.868,348.878 r90 top
C54 "1uF" "CAP 0402/1005 RF" 439.768,348.878 r90 top
C55 "0.1µF" "CAP 0201/0603 RF" 99.822,158.808 r90 top
C56 "0.1µF" "CAP 0201/0603 RF" 97.917,158.808 r90 top
C57 "0.1µF" "CAP 0201/0603 RF" 96.774,157.157 r270 top
C58 "10µF" "CAP 0402/1005 RF" 97.917,157.163 r270 top
C59 "0.1µF" "CAP 0201/0603 RF" 442.904,348.488 r180 top
C60 "0.1µF" "CAP 0201/0603 RF" 442.905,347.735 r180 top
C61 "0.1µF" "CAP 0201/0603 RF" 442.904,347.036 r180 top
C62 "10µF" "CAP 0402/1005 RF" 443.035,346.188 r180 top
C63 "100nF" "CAP 0402/1005 RF" 327.063,171.324 r270 top
C64 "100nF" "CAP 0402/1005 RF" 336.19,174.88 r0 top
C65 "0.1µF" "CAP 0201/0603 RF" 100.711,158.814 r90 top
C66 "0.1µF" "CAP 0201/0603 RF" 97.028,158.814 r90 top
C67 "100nF" "CAP 0402/1005 RF" 330.453,174.88 r270 top
C68 "10nF" "CAP 0201/0603 RF" 101.219,157.163 r270 top
C69 "10µF" "CAP 0402/1005 RF" 99.822,157.163 r270 top
C70 "100nF" "CAP 0402/1005 RF" 327.953,171.324 r270 top
C71 "0.1µF" "CAP 0201/0603 RF" 441.521,331.933 r270 top
C72 "0.1µF" "CAP 0201/0603 RF" 442.779,331.933 r270 top
C73 "0.1µF" "CAP 0201/0603 RF" 444.038,331.933 r90 top
C74 "10µF" "CAP 0402/1005 RF" 440.113,331.608 r90 top
C75 "100nF" "CAP 0402/1005 RF" 338.204,179.764 r0 top
C76 "100nF" "CAP 0402/1005 RF" 338.204,181.992 r0 top
C77 "100nF" "CAP 0402/1005 RF" 322.583,180.264 r180 top
C78 "10uF" "CAP 0402/1005 RF" 329.453,174.88 r90 top
C79 "10uF" "CAP 0402/1005 RF" 330.953,190.423 r270 top
C80 "10uF" "CAP 0402/1005 RF" 324.548,190.423 r270 top
C81 "100nF" "CAP 0402/1005 RF" 322.583,178.264 r180 top
C82 "100nF" "CAP 0402/1005 RF" 338.204,184.264 r0 top
C83 "100nF" "CAP 0402/1005 RF" 322.583,185.111 r180 top
C84 "0.1µF" "CAP 0201/0603 RF" 446.531,345.013 r270 top
C85 "0.1µF" "CAP 0201/0603 RF" 447.254,345.011 r270 top
C86 "10nF" "CAP 0201/0603 RF" 446.041,341.952 r90 top
C87 "10µF" "CAP 0402/1005 RF" 445.151,341.952 r90 top
C88 "100nF" "CAP 0402/1005 RF" 322.583,186.111 r180 top
C89 "100nF" "CAP 0402/1005 RF" 331.953,190.423 r90 top
C90 "100nF" "CAP 0402/1005 RF" 329.013,190.423 r90 top
C91 "100nF" "CAP 0402/1005 RF" 329.953,190.423 r90 top
C92 "100nF" "CAP 0402/1005 RF" 338.204,178.764 r0 top
C93 "100nF" "CAP 0402/1005 RF" 329.949,171.324 r270 top
C94 "0.1µF" "CAP 0201/0603 RF" 476.172,403.219 r0 top
C95 "0.1µF" "CAP 0201/0603 RF" 476.172,406.521 r0 top
C96 "100nF" "CAP 0402/1005 RF" 325.548,190.423 r90 top
C97 "10nF" "CAP 0201/0603 RF" 478.328,407.918 r0 top
C98 "10µF" "CAP 0402/1005 RF" 478.328,407.029 r0 top
C99 "100nF" "CAP 0402/1005 RF" 321.5,171.393 r90 top
C100 "100nF" "CAP 0402/1005 RF" 345.697,183.747 r90 top
C101 "10uF" "CAP 0402/1005 RF" 325.31,171.402 r90 top
C102 "10uF" "CAP 0402/1005 RF" 341.751,183.747 r90 top
C103 "100nF" "CAP 0402/1005 RF" 336.19,169.929 r180 top
C104 "100nF" "CAP 0402/1005 RF" 316.732,184.154 r90 top
C105 "10uF" "CAP 0402/1005 RF" 336.19,173.875 r180 top
C106 "10uF" "CAP 0402/1005 RF" 320.678,184.154 r90 top
C107 "100nF" "CAP 0402/1005 RF" 331.732,165.473 r180 top
C108 "100nF" "CAP 0402/1005 RF" 321.491,192.756 r0 top
C109 "10uF" "CAP 0402/1005 RF" 331.732,169.419 r180 top
C110 "10uF" "CAP 0402/1005 RF" 321.491,188.81 r0 top
C111 "10nF" "CAP 0201/0603 RF" 270.701,112.87 r90 top
C112 "10nF" "CAP 0201/0603 RF" 271.928,112.87 r90 top
C113 "10nF" "CAP 0201/0603 RF" 276.839,112.87 r90 top
C114 "10nF" "CAP 0201/0603 RF" 280.522,112.87 r90 top
C115 "10nF" "CAP 0201/0603 RF" 277.793,194.739 r90 top
C116 "10nF" "CAP 0201/0603 RF" 279.294,112.87 r90 top
C117 "10nF" "CAP 0201/0603 RF" 269.473,112.87 r90 top
C118 "10nF" "CAP 0201/0603 RF" 268.245,112.87 r90 top
C119 "10nF" "CAP 0201/0603 RF" 275.611,112.87 r90 top
C120 "10nF" "CAP 0201/0603 RF" 279.021,194.739 r90 top
C121 "10nF" "CAP 0201/0603 RF" 273.156,112.87 r90 top
C122 "10nF" "CAP 0201/0603 RF" 274.384,112.87 r90 top
C123 "10nF" "CAP 0201/0603 RF" 278.067,112.87 r90 top
C124 "100nF" "CAP 0402/1005 RF" 327.453,165.473 r180 top
C125 "100nF" "CAP 0402/1005 RF" 332.343,196.978 r180 top
C126 "10uF" "CAP 0402/1005 RF" 327.453,169.419 r180 top
C127 "10uF" "CAP 0402/1005 RF" 332.343,193.032 r180 top
C128 "1uF" "CAP 0402/1005 RF" 269.006,114.47 r90 top
C129 "1uF" "CAP 0402/1005 RF" 276.976,114.47 r90 top
C130 "1uF" "CAP 0402/1005 RF" 270.6,114.47 r90 top
C131 "1uF" "CAP 0402/1005 RF" 278.571,114.47 r90 top
C132 "1uF" "CAP 0402/1005 RF" 283.353,114.47 r90 top
C133 "1uF" "CAP 0402/1005 RF" 265.817,114.47 r90 top
C134 "1uF" "CAP 0402/1005 RF" 273.788,114.47 r90 top
C135 "1uF" "CAP 0402/1005 RF" 272.194,114.47 r90 top
C136 "1uF" "CAP 0402/1005 RF" 280.165,114.47 r90 top
C137 "1uF" "CAP 0402/1005 RF" 284.947,114.47 r90 top
C138 "1uF" "CAP 0402/1005 RF" 267.411,114.47 r90 top
C139 "1uF" "CAP 0402/1005 RF" 275.382,114.47 r90 top
C140 "1uF" "CAP 0402/1005 RF" 281.759,114.47 r90 top
C141 "100nF" "CAP 0402/1005 RF" 345.737,179.227 r270 top
C142 "100nF" "CAP 0402/1005 RF" 328.523,196.978 r0 top
C143 "10uF" "CAP 0402/1005 RF" 341.791,179.227 r270 top
C144 "10uF" "CAP 0402/1005 RF" 328.523,193.032 r0 top
C145 "100nF" "CAP 0402/1005 RF" 345.697,181.602 r90 top
C146 "100nF" "CAP 0402/1005 RF" 345.737,177.03 r270 top
C147 "10uF" "CAP 0402/1005 RF" 341.751,181.602 r90 top
C148 "10uF" "CAP 0402/1005 RF" 341.791,177.03 r270 top
C149 "10nF" "CAP 0201/0603 RF" 279.836,116.623 r90 top
C150 "10nF" "CAP 0201/0603 RF" 283.454,116.623 r90 top
C151 "10nF" "CAP 0201/0603 RF" 278.931,116.623 r90 top
C152 "10nF" "CAP 0201/0603 RF" 281.645,116.623 r90 top
C153 "10nF" "CAP 0201/0603 RF" 277.122,116.623 r90 top
C154 "10nF" "CAP 0201/0603 RF" 282.55,116.623 r90 top
C155 "10nF" "CAP 0201/0603 RF" 278.027,116.623 r90 top
C156 "10nF" "CAP 0201/0603 RF" 280.74,116.623 r90 top
C157 "10nF" "CAP 0201/0603 RF" 276.217,116.623 r90 top
C158 "10nF" "CAP 0201/0603 RF" 286.106,116.635 r90 top
C159 "10nF" "CAP 0201/0603 RF" 285.263,116.623 r90 top
C160 "10nF" "CAP 0201/0603 RF" 286.868,116.635 r90 top
C161 "10nF" "CAP 0201/0603 RF" 284.359,116.623 r90 top
C162 "100nF" "CAP 0402/1005 RF" 316.868,180.822 r270 top
C163 "100nF" "CAP 0402/1005 RF" 329.559,165.473 r180 top
C164 "10uF" "CAP 0402/1005 RF" 320.678,180.822 r90 top
C165 "10uF" "CAP 0402/1005 RF" 329.559,169.419 r180 top
C166 "10nF" "CAP 0201/0603 RF" 265.278,116.623 r90 top
C167 "10nF" "CAP 0201/0603 RF" 269.141,116.623 r90 top
C168 "10nF" "CAP 0201/0603 RF" 273.003,116.623 r90 top
C169 "10nF" "CAP 0201/0603 RF" 266.05,116.623 r90 top
C170 "10nF" "CAP 0201/0603 RF" 269.913,116.623 r90 top
C171 "10nF" "CAP 0201/0603 RF" 266.823,116.623 r90 top
C172 "10nF" "CAP 0201/0603 RF" 270.686,116.623 r90 top
C173 "10nF" "CAP 0201/0603 RF" 274.549,116.623 r90 top
C174 "10nF" "CAP 0201/0603 RF" 268.368,116.623 r90 top
C175 "10nF" "CAP 0201/0603 RF" 271.458,116.623 r90 top
C176 "10nF" "CAP 0201/0603 RF" 273.776,116.623 r90 top
C177 "10nF" "CAP 0201/0603 RF" 267.595,116.623 r90 top
C178 "10nF" "CAP 0201/0603 RF" 272.231,116.623 r90 top
C179 "100nF" "CAP 0402/1005 RF" 316.632,178.173 r90 top
C180 "10uF" "CAP 0402/1005 RF" 320.678,178.173 r90 top
C181 "1uF" "CAP 0402/1005 RF" 280.899,120.3 r90 top
C182 "1uF" "CAP 0402/1005 RF" 263.373,120.3 r90 top
C183 "1uF" "CAP 0402/1005 RF" 272.136,120.3 r90 top
C184 "1uF" "CAP 0402/1005 RF" 264.833,120.3 r90 top
C185 "1uF" "CAP 0402/1005 RF" 273.596,120.3 r90 top
C186 "1uF" "CAP 0402/1005 RF" 270.675,120.3 r90 top
C187 "1uF" "CAP 0402/1005 RF" 279.438,120.3 r90 top
C188 "1uF" "CAP 0402/1005 RF" 266.294,120.3 r90 top
C189 "1uF" "CAP 0402/1005 RF" 275.057,120.3 r90 top
C190 "1uF" "CAP 0402/1005 RF" 269.215,120.3 r90 top
C191 "1uF" "CAP 0402/1005 RF" 277.978,120.3 r90 top
C192 "1uF" "CAP 0402/1005 RF" 267.754,120.3 r90 top
C193 "1uF" "CAP 0402/1005 RF" 276.517,120.3 r90 top
C194 "1uF" "CAP 0402/1005 RF" 271.062,123.239 r90 top
C195 "1uF" "CAP 0402/1005 RF" 280.616,123.239 r90 top
C196 "1uF" "CAP 0402/1005 RF" 277.432,123.239 r90 top
C197 "1uF" "CAP 0402/1005 RF" 269.47,123.239 r90 top
C198 "1uF" "CAP 0402/1005 RF" 282.209,123.239 r90 top
C199 "1uF" "CAP 0402/1005 RF" 275.839,123.239 r90 top
C200 "1uF" "CAP 0402/1005 RF" 274.247,123.239 r90 top
C201 "1uF" "CAP 0402/1005 RF" 279.024,123.239 r90 top
C202 "1uF" "CAP 0402/1005 RF" 272.655,123.239 r90 top
C203 "1uF" "CAP 0402/1005 RF" 263.101,123.239 r90 top
C204 "1uF" "CAP 0402/1005 RF" 266.285,123.239 r90 top
C205 "1uF" "CAP 0402/1005 RF" 264.693,123.239 r90 top
C206 "1uF" "CAP 0402/1005 RF" 267.878,123.239 r90 top
C207 "100nF" "CAP 0402/1005 RF" 57.404,205.613 r0 top
C208 "22uF" "CAP 1210/3225 - 1MM" 63.246,204.47 r0 top
C209 "100nF" "CAP 0402/1005 RF" 67.945,205.613 r0 top
C210 "22uF" "CAP 1210/3225 - 1MM" 73.66,204.47 r0 top
C211 "100nF" "CAP 0402/1005 RF" 67.945,170.434 r180 top
C212 "22uF" "CAP 1210/3225 - 1MM" 332.486,92.456 r0 top
C213 "100nF" "CAP 0402/1005 RF" 63.246,195.746 r0 top
C214 "22uF" "CAP 1210/3225 - 1MM" 71.247,184.404 r0 top
C215 "100nF" "CAP 0402/1005 RF" 63.246,197.524 r0 top
C216 "22uF" "CAP 1210/3225 - 1MM" 71.374,191.389 r0 top
C217 "100nF" "CAP 0402/1005 RF" 63.246,196.635 r0 top
C218 "22uF" "CAP 1210/3225 - 1MM" 71.374,187.833 r0 top
C219 "100nF" "CAP 0402/1005 RF" 177.029,251.222 r90 top
C220 "100nF" "CAP 0402/1005 RF" 180.425,251.206 r90 top
C221 "100nF" "CAP 0402/1005 RF" 174.473,251.222 r90 top
C222 "100nF" "CAP 0402/1005 RF" 179.426,251.206 r90 top
C223 "4.7uF" "CAP 0402/1005 RF" 142.937,241.757 r0 top
C224 "470nF" "CAP 0402/1005 RF" 146.685,239.598 r0 top
C225 "470nF" "CAP 0402/1005 RF" 139.201,235.28 r0 top
C226 "68nF" "CAP 0402/1005 RF" 149.283,240.741 r0 top
C227 "68nF" "CAP 0402/1005 RF" 139.192,237.185 r0 top
C228 "4.7uF" "CAP 0402/1005 RF" 146.558,240.614 r0 top
C229 "470nF" "CAP 0402/1005 RF" 149.274,239.598 r0 top
C230 "470nF" "CAP 0402/1005 RF" 139.183,236.296 r0 top
C231 "68nF" "CAP 0402/1005 RF" 139.192,241.757 r0 top
C232 "68nF" "CAP 0402/1005 RF" 142.937,239.344 r0 top
C233 "4.7uF" "CAP 0402/1005 RF" 149.283,237.566 r0 top
C234 "470nF" "CAP 0402/1005 RF" 139.192,240.868 r0 top
C235 "470nF" "CAP 0402/1005 RF" 142.937,238.201 r0 top
C236 "68nF" "CAP 0402/1005 RF" 142.928,240.614 r0 top
C237 "68nF" "CAP 0402/1005 RF" 146.676,238.709 r0 top
C238 "4.7uF" "CAP 0402/1005 RF" 149.274,236.55 r0 top
C239 "470nF" "CAP 0402/1005 RF" 139.192,239.979 r0 top
C240 "470nF" "CAP 0402/1005 RF" 142.937,237.185 r0 top
C241 "68nF" "CAP 0402/1005 RF" 146.685,235.788 r0 top
C242 "68nF" "CAP 0402/1005 RF" 146.685,236.677 r0 top
C243 "100nF" "CAP 0402/1005 RF" 146.685,232.621 r0 top
C244 "100nF" "CAP 0402/1005 RF" 149.292,238.582 r180 top
C245 "100nF" "CAP 0402/1005 RF" 142.875,231.859 r0 top
C246 "100nF" "CAP 0402/1005 RF" 146.685,237.693 r180 top
C247 "4.7uF" "CAP 0402/1005 RF" 139.201,234.391 r0 top
C248 "470nF" "CAP 0402/1005 RF" 150.495,231.605 r0 top
C249 "470nF" "CAP 0402/1005 RF" 149.283,235.534 r0 top
C250 "68nF" "CAP 0402/1005 RF" 139.201,239.09 r0 top
C251 "68nF" "CAP 0402/1005 RF" 142.866,236.042 r0 top
C252 "4.7uF" "CAP 0402/1005 RF" 152.391,236.55 r0 top
C253 "470nF" "CAP 0402/1005 RF" 152.391,238.455 r0 top
C254 "470nF" "CAP 0402/1005 RF" 152.4,239.344 r0 top
C255 "68nF" "CAP 0402/1005 RF" 139.192,238.201 r0 top
C256 "68nF" "CAP 0402/1005 RF" 142.875,235.026 r0 top
C257 "4.7uF" "CAP 0402/1005 RF" 152.391,237.439 r0 top
C258 "470nF" "CAP 0402/1005 RF" 155.566,238.709 r0 top
C259 "470nF" "CAP 0402/1005 RF" 155.693,236.55 r0 top
C260 "68nF" "CAP 0402/1005 RF" 155.566,240.614 r0 top
C261 "68nF" "CAP 0402/1005 RF" 155.566,242.519 r0 top
C262 "4.7uF" "CAP 0402/1005 RF" 155.566,237.693 r0 top
C263 "470nF" "CAP 0402/1005 RF" 155.693,235.534 r0 top
C264 "470nF" "CAP 0402/1005 RF" 155.566,239.598 r0 top
C265 "68nF" "CAP 0402/1005 RF" 155.566,241.503 r0 top
C266 "68nF" "CAP 0402/1005 RF" 152.391,235.534 r0 top
C267 "100nF" "CAP 0201/0603 RF" 256.652,176.752 r270 top
C268 "100nF" "CAP 0201/0603 RF" 255.89,176.625 r270 top
C269 "100nF" "CAP 0201/0603 RF" 253.731,177 r270 top
C270 "100nF" "CAP 0201/0603 RF" 252.969,177.012 r270 top
C271 "100nF" "CAP 0201/0603 RF" 283.718,157.311 r90 bottom
C272 "100nF" "CAP 0201/0603 RF" 284.635,157.379 r270 bottom
C273 "10nF" "CAP 0201/0603 RF" 174.201,160.765 r90 top
C274 "100nF" "CAP 0201/0603 RF" 287.528,157.039 r90 bottom
C275 "100nF" "CAP 0201/0603 RF" 286.639,156.791 r90 bottom
C276 "10nF" "CAP 0201/0603 RF" 173.368,160.764 r90 top
C277 "10nF" "CAP 0201/0603 RF" 176.62,156.21 r0 top
C278 "10nF" "CAP 0201/0603 RF" 174.976,156.21 r0 top
C279 "100nF" "CAP 0201/0603 RF" 139.383,136.283 r270 bottom
C280 "100nF" "CAP 0201/0603 RF" 138.633,136.283 r270 bottom
C281 "100nF" "CAP 0201/0603 RF" 136.516,136.283 r270 bottom
C282 "100nF" "CAP 0201/0603 RF" 135.726,136.283 r270 bottom
C283 "100nF" "CAP 0201/0603 RF" 130.556,129.794 r90 bottom
C284 "100nF" "CAP 0201/0603 RF" 131.299,129.794 r90 bottom
C285 "10nF" "CAP 0201/0603 RF" 172.677,160.765 r90 top
C286 "100nF" "CAP 0201/0603 RF" 133.258,129.794 r90 bottom
C287 "100nF" "CAP 0201/0603 RF" 133.943,129.794 r90 bottom
C288 "10nF" "CAP 0201/0603 RF" 174.963,160.765 r90 top
C289 "10nF" "CAP 0201/0603 RF" 147.522,171.403 r0 top
C290 "10nF" "CAP 0201/0603 RF" 145.929,171.323 r0 top
C291 "100nF" "CAP 0201/0603 RF" 301.32,95.637 r90 bottom
C292 "100nF" "CAP 0201/0603 RF" 302.082,95.637 r90 bottom
C293 "100nF" "CAP 0201/0603 RF" 304.368,95.637 r90 bottom
C294 "100nF" "CAP 0201/0603 RF" 305.13,95.637 r90 bottom
C295 "100nF" "CAP 0201/0603 RF" 308.082,95.637 r90 bottom
C296 "100nF" "CAP 0201/0603 RF" 307.32,95.637 r90 bottom
C297 "10nF" "CAP 0201/0603 RF" 171.069,160.776 r90 top
C298 "100nF" "CAP 0201/0603 RF" 311.152,95.637 r90 bottom
C299 "100nF" "CAP 0201/0603 RF" 310.39,95.637 r90 bottom
C300 "10nF" "CAP 0201/0603 RF" 171.831,160.776 r90 top
C301 "10nF" "CAP 0201/0603 RF" 147.522,172.8 r0 top
C302 "10nF" "CAP 0201/0603 RF" 145.929,172.72 r0 top
C303_I2C_Bridge "100nF" "CAP 0402/1005 RF" 360.832,74.549 r90 top (schematic designator C303)
C303_I2C_Bridge_2 "100nF" "CAP 0402/1005 RF" 97.917,262.251 r0 top (schematic designator C303)
C303_I2C_Bridge_3 "100nF" "CAP 0402/1005 RF" 360.832,81.026 r90 top (schematic designator C303)
C304 "4.7µF" "CAP 0603/1608 RF" 241.724,244.523 r270 top
C305 "4.7µF" "CAP 0603/1608 RF" 242.849,253.891 r90 top
C306 "4.7µF" "CAP 0603/1608 RF" 243.099,244.523 r270 top
C307 "4.7µF" "CAP 0603/1608 RF" 241.424,253.891 r90 top
C308 "4.7 µF" "CAP 0603/1608 RF" 221.709,243.898 r270 top
C309_U_Pomiar_pradu_napiecia_1 "100nF" "CAP 0402/1005 RF" 360.832,123.85 r90 top (schematic designator C309)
